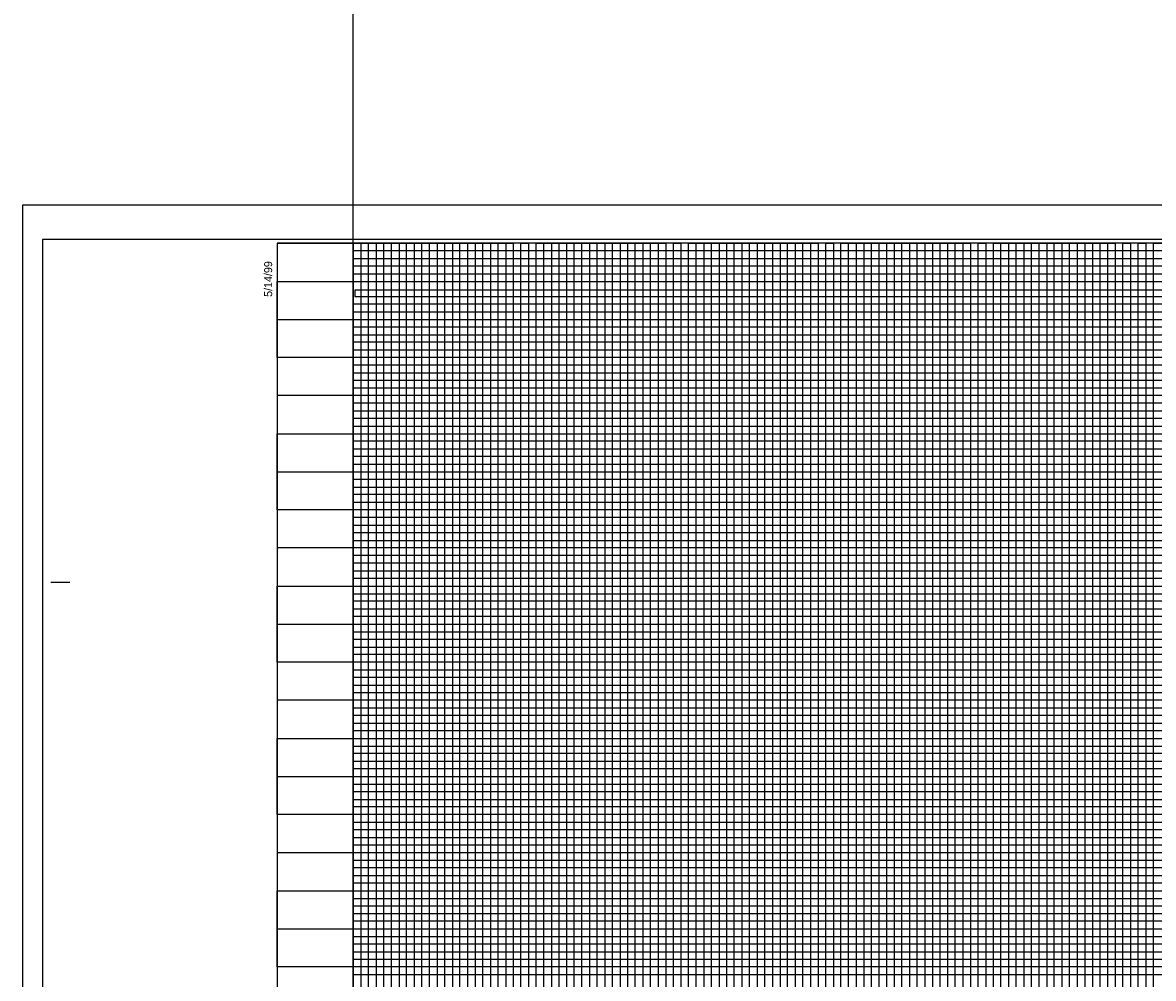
# Model space of a CAD drawing. Extents: x 2345490 to 2436403, y 465165 to 573888.
# Drawn here: x 2381550 to 2382292, y 532954 to 533581 of the extents above; entities that cross this region are included whole.
import ezdxf

# ---------------------------------------------------------------- set-up
doc = ezdxf.new("R2010")
doc.units = 0
for name, color, linetype in [('Old_Level_18', 7, 'Continuous'), ('Old_Level_41', 7, 'Continuous'), ('Old_Level_42', 7, 'Continuous'), ('Old_Level_43', 7, 'Continuous'), ('Old_Level_50', 7, 'Continuous'), ('Old_Level_51', 7, 'Continuous'), ('Old_Level_63', 7, 'Continuous')]:
    doc.layers.add(name, color=color, linetype=linetype)

msp = doc.modelspace()

# ---------------------------------------------------------------- linework, layer by layer
at = {"layer": 'Old_Level_18'}
msp.add_lwpolyline([(2383216.79875, 533436.04975), (2381716.79875, 533436.04975), (2381716.79875, 532386.04975), (2383216.79875, 532386.04975)], close=True, dxfattribs=at)
at = {"layer": 'Old_Level_41'}
msp.add_line((2381568.29875, 533213.54975), (2381580.79875, 533213.54975), dxfattribs=at)
for points in [[(2381716.79875, 533436.04975), (2381766.79875, 533436.04975), (2381766.79875, 532411.04975), (2381816.79875, 532411.04975), (2381816.79875, 533436.04975), (2381866.79875, 533436.04975), (2381866.79875, 532411.04975), (2381916.79875, 532411.04975), (2381916.79875, 533436.04975), (2381966.79875, 533436.04975), (2381966.79875, 532411.04975), (2382016.79875, 532411.04975), (2382016.79875, 533436.04975), (2382066.79875, 533436.04975), (2382066.79875, 532411.04975), (2382116.79875, 532411.04975), (2382116.79875, 533436.04975), (2382166.79875, 533436.04975), (2382166.79875, 532411.04975), (2382216.79875, 532411.04975), (2382216.79875, 533436.04975), (2382266.79875, 533436.04975), (2382266.79875, 532411.04975), (2382316.79875, 532411.04975)], [(2381791.79875, 532411.04975), (2381791.79875, 533436.04975), (2381841.79875, 533436.04975), (2381841.79875, 532411.04975), (2381891.79875, 532411.04975), (2381891.79875, 533436.04975), (2381941.79875, 533436.04975), (2381941.79875, 532411.04975), (2381991.79875, 532411.04975), (2381991.79875, 533436.04975), (2382041.79875, 533436.04975), (2382041.79875, 532411.04975), (2382091.79875, 532411.04975), (2382091.79875, 533436.04975), (2382141.79875, 533436.04975), (2382141.79875, 532411.04975), (2382191.79875, 532411.04975), (2382191.79875, 533436.04975), (2382241.79875, 533436.04975), (2382241.79875, 532411.04975), (2382291.79875, 532411.04975), (2382291.79875, 533436.04975), (2382341.79875, 533436.04975)], [(2381716.79875, 533386.04975), (2383016.74875, 533386.04975)], [(2383016.74875, 533336.04975), (2381716.79875, 533336.04975), (2381716.79875, 533285.99975), (2383216.79875, 533285.99975)], [(2383216.79875, 533261.04975), (2381716.79875, 533261.04975), (2381716.79875, 533311.04975), (2383016.74875, 533311.04975)], [(2383216.79875, 533236.04975), (2381716.79875, 533236.04975), (2381716.79875, 533186.04975), (2383216.79875, 533186.04975)], [(2383216.79875, 533161.04975), (2381716.79875, 533161.04975), (2381716.79875, 533211.04975), (2383216.79875, 533211.04975)], [(2383216.79875, 533136.04975), (2381716.79875, 533136.04975), (2381716.79875, 533086.04975), (2383216.79875, 533086.04975)], [(2383216.79875, 533036.04975), (2381716.79875, 533036.04975), (2381716.79875, 532986.04975), (2383216.79875, 532986.04975)]]:
    msp.add_lwpolyline(points, dxfattribs=at)
at = {"layer": 'Old_Level_42'}
for points in [[(2383016.74875, 533361.04975), (2381716.89875, 533361.04975), (2381716.89875, 533410.99975), (2383016.74875, 533410.99975)], [(2383216.79875, 533061.04975), (2381716.79875, 533061.04975), (2381716.79875, 533111.04975), (2383216.79875, 533111.04975)], [(2383216.79875, 532961.04975), (2381716.79875, 532961.04975), (2381716.79875, 533011.04975), (2383216.79875, 533011.04975)]]:
    msp.add_lwpolyline(points, dxfattribs=at)
at = {"layer": 'Old_Level_43'}
for p, q in [((2383166.79875, 533256.04975), (2381766.79875, 533256.04975)), ((2381766.79875, 533256.04975), (2381766.79875, 533251.04975)), ((2381766.79875, 533251.04975), (2383166.79875, 533251.04975)), ((2383166.79875, 533231.04975), (2381766.79875, 533231.04975))]:
    msp.add_line(p, q, dxfattribs=at)
for points in [[(2381771.79875, 533436.04975), (2381776.79875, 533436.04975), (2381781.79875, 533436.04975), (2381786.79875, 533436.04975), (2381796.79875, 533436.04975), (2381763.74875, 533436.04975), (2381768.74875, 533436.04975), (2381726.79875, 533436.04975), (2381731.79875, 533436.04975), (2381736.79875, 533436.04975), (2381746.79875, 533436.04975), (2381751.79875, 533436.04975), (2381756.79875, 533436.04975), (2381761.79875, 533436.04975), (2381771.79875, 533436.04975), (2381771.79875, 532411.04975)], [(2381776.79875, 532411.04975), (2381776.79875, 533436.04975), (2381781.79875, 533436.04975), (2381781.79875, 532411.04975)], [(2381786.79875, 532411.04975), (2381786.79875, 533436.04975), (2381796.79875, 533436.04975), (2381796.79875, 532411.04975)], [(2381801.79875, 532411.04975), (2381801.79875, 533436.04975), (2381806.79875, 533436.04975), (2381806.79875, 532411.04975)], [(2381811.79875, 532411.04975), (2381811.79875, 533436.04975), (2381821.79875, 533436.04975), (2381821.79875, 532411.04975)], [(2381826.79875, 532411.04975), (2381826.79875, 533436.04975), (2381831.79875, 533436.04975), (2381831.79875, 532411.04975)], [(2381836.79875, 532411.04975), (2381836.79875, 533436.04975), (2381846.79875, 533436.04975), (2381846.79875, 532411.04975)], [(2381851.79875, 532411.04975), (2381851.79875, 533436.04975), (2381856.79875, 533436.04975), (2381856.79875, 532411.04975)], [(2381861.79875, 532411.04975), (2381861.79875, 533436.04975), (2381871.79875, 533436.04975), (2381871.79875, 532411.04975)], [(2381876.79875, 532411.04975), (2381876.79875, 533436.04975), (2381881.79875, 533436.04975), (2381881.79875, 532411.04975)], [(2381886.79875, 532411.04975), (2381886.79875, 533436.04975), (2381896.79875, 533436.04975), (2381896.79875, 532411.04975)], [(2381901.79875, 532411.04975), (2381901.79875, 533436.04975), (2381906.79875, 533436.04975), (2381906.79875, 532411.04975)], [(2381911.79875, 532411.04975), (2381911.79875, 533436.04975), (2381921.79875, 533436.04975), (2381921.79875, 532411.04975)], [(2381926.79875, 532411.04975), (2381926.79875, 533436.04975), (2381931.79875, 533436.04975), (2381931.79875, 532411.04975)], [(2381936.79875, 532411.04975), (2381936.79875, 533436.04975), (2381946.79875, 533436.04975), (2381946.79875, 532411.04975)], [(2381951.79875, 532411.04975), (2381951.79875, 533436.04975), (2381956.79875, 533436.04975), (2381956.79875, 532411.04975)], [(2381961.79875, 532411.04975), (2381961.79875, 533436.04975), (2381971.79875, 533436.04975), (2381971.79875, 532411.04975)], [(2381976.79875, 532411.04975), (2381976.79875, 533436.04975), (2381976.79875, 533436.04975), (2381981.79875, 533436.04975), (2381981.79875, 532411.04975)], [(2381986.79875, 532411.04975), (2381986.79875, 533436.04975), (2381996.79875, 533436.04975), (2381996.79875, 532411.04975)], [(2382001.79875, 532411.04975), (2382001.79875, 533436.04975), (2382006.79875, 533436.04975), (2382006.79875, 532411.04975)], [(2382011.79875, 532411.04975), (2382011.79875, 533436.04975), (2382021.79875, 533436.04975), (2382021.79875, 532411.04975)], [(2382026.79875, 532411.04975), (2382026.79875, 533436.04975), (2382031.79875, 533436.04975), (2382031.79875, 532411.04975)], [(2382036.79875, 532411.04975), (2382036.79875, 533436.04975), (2382046.79875, 533436.04975), (2382046.79875, 532411.04975)], [(2382051.79875, 532411.04975), (2382051.79875, 533436.04975), (2382056.79875, 533436.04975), (2382056.79875, 532411.04975)], [(2382061.79875, 532411.04975), (2382061.79875, 533436.04975), (2382071.79875, 533436.04975), (2382071.79875, 532411.04975)], [(2382076.79875, 532411.04975), (2382076.79875, 533436.04975), (2382081.79875, 533436.04975), (2382081.79875, 532411.04975)], [(2382086.79875, 532411.04975), (2382086.79875, 533436.04975), (2382096.79875, 533436.04975), (2382096.79875, 532411.04975)], [(2382101.79875, 533436.04975), (2382101.79875, 532411.04975), (2382106.79875, 532411.04975), (2382106.79875, 533436.04975)], [(2382101.79875, 533435.44975), (2382101.79875, 532411.04975), (2382106.79875, 532411.04975), (2382106.79875, 533435.44975)], [(2382111.79875, 532411.04975), (2382111.79875, 533436.04975), (2382121.79875, 533436.04975), (2382121.79875, 532411.04975)], [(2382126.79875, 532411.04975), (2382126.79875, 533436.04975), (2382131.79875, 533436.04975), (2382131.79875, 532411.04975)], [(2382136.79875, 532411.04975), (2382136.79875, 533436.04975), (2382146.79875, 533436.04975), (2382146.79875, 532411.04975)], [(2382151.79875, 532411.04975), (2382151.79875, 533436.04975), (2382156.79875, 533436.04975), (2382156.79875, 532411.04975)], [(2382161.79875, 532411.04975), (2382161.79875, 533436.04975), (2382171.79875, 533436.04975), (2382171.79875, 532411.04975)], [(2382176.79875, 532411.04975), (2382176.79875, 533436.04975), (2382181.79875, 533436.04975), (2382181.79875, 532411.04975)], [(2382186.79875, 532411.04975), (2382186.79875, 533436.04975), (2382196.79875, 533436.04975), (2382196.79875, 532411.04975)], [(2382201.79875, 532411.04975), (2382201.79875, 533436.04975), (2382206.79875, 533436.04975), (2382206.79875, 532411.04975)], [(2382211.79875, 532411.04975), (2382211.79875, 533436.04975), (2382221.79875, 533436.04975), (2382221.79875, 532411.04975)], [(2382226.79875, 532411.04975), (2382226.79875, 533436.04975), (2382231.79875, 533436.04975), (2382231.79875, 532411.04975)], [(2382236.79875, 532411.04975), (2382236.79875, 533436.04975), (2382246.79875, 533436.04975), (2382246.79875, 532411.04975)], [(2382251.79875, 533436.04975), (2382251.79875, 532411.04975), (2382256.79875, 532411.04975), (2382256.79875, 533436.04975), (2382261.79875, 533436.04975), (2382261.79875, 532411.04975), (2382271.79875, 532411.04975), (2382271.79875, 533436.04975), (2382276.79875, 533436.04975), (2382276.79875, 532411.04975), (2382281.79875, 532411.04975), (2382281.79875, 533436.04975), (2382286.79875, 533436.04975), (2382286.79875, 532411.04975)], [(2383016.74875, 533431.04975), (2381766.79875, 533431.04975), (2381766.79875, 533426.04975), (2383016.74875, 533426.04975)], [(2383016.74875, 533421.04975), (2381766.79875, 533421.04975), (2381766.79875, 533416.04975), (2383016.74875, 533416.04975)], [(2383016.74875, 533405.29975), (2381767.79875, 533405.29975), (2381767.79875, 533401.04975), (2383016.74875, 533401.04975)], [(2383016.74875, 533396.04975), (2381766.79875, 533396.04975), (2381766.79875, 533391.04975), (2383016.74875, 533391.04975)], [(2383016.74875, 533381.04975), (2381766.79875, 533381.04975), (2381766.79875, 533376.04975), (2383016.74875, 533376.04975)], [(2383016.74875, 533371.04975), (2381766.79875, 533371.04975), (2381766.79875, 533366.04975), (2383016.74875, 533366.04975)], [(2383016.74875, 533356.04975), (2381766.79875, 533356.04975), (2381766.79875, 533351.04975), (2383016.74875, 533351.04975)], [(2383016.74875, 533346.04975), (2381766.79875, 533346.04975), (2381766.79875, 533341.04975), (2383016.74875, 533341.04975)], [(2383016.74875, 533331.04975), (2381766.79875, 533331.04975), (2381766.79875, 533326.04975), (2383016.74875, 533326.04975)], [(2383016.74875, 533321.04975), (2381766.79875, 533321.04975), (2381766.79875, 533316.04975), (2383016.74875, 533316.04975)], [(2383016.74875, 533306.04975), (2381766.79875, 533306.04975), (2381766.79875, 533301.04975), (2383016.74875, 533301.04975)], [(2383166.79875, 533296.04975), (2381766.79875, 533296.04975), (2381766.79875, 533296.04975), (2381766.79875, 533276.04975), (2383166.79875, 533276.04975)], [(2381766.79875, 533291.04975), (2383166.79875, 533291.04975)], [(2383166.79875, 533281.04975), (2381766.79875, 533281.04975)], [(2383166.79875, 533271.04975), (2381766.79875, 533271.04975), (2381766.79875, 533266.04975), (2383166.79875, 533266.04975)], [(2383166.79875, 533246.04975), (2381766.79875, 533246.04975), (2381766.79875, 533241.04975), (2383166.79875, 533241.04975)], [(2383166.79875, 533226.04975), (2381766.79875, 533226.04975), (2381766.79875, 533221.04975), (2383166.79875, 533221.04975)], [(2383166.79875, 533216.04975), (2381766.79875, 533216.04975)], [(2381766.79875, 533206.04975), (2383166.79875, 533206.04975)], [(2383166.79875, 533201.04975), (2381766.79875, 533201.04975), (2381766.79875, 533196.04975), (2383166.79875, 533196.04975)], [(2383166.79875, 533191.04975), (2381766.79875, 533191.04975), (2381766.79875, 533181.04975), (2383166.79875, 533181.04975)], [(2383166.79875, 533176.04975), (2381766.79875, 533176.04975), (2381766.79875, 533171.04975), (2383166.79875, 533171.04975)], [(2383166.79875, 533166.04975), (2381766.79875, 533166.04975), (2381766.79875, 533156.04975), (2383166.79875, 533156.04975)], [(2383166.79875, 533151.04975), (2381766.79875, 533151.04975), (2381766.79875, 533146.04975), (2383166.79875, 533146.04975)], [(2383166.79875, 533141.04975), (2381766.79875, 533141.04975), (2381766.79875, 533131.04975), (2383166.79875, 533131.04975)], [(2383166.79875, 533126.04975), (2381766.79875, 533126.04975), (2381766.79875, 533121.04975), (2383166.79875, 533121.04975)], [(2383166.79875, 533116.04975), (2381766.79875, 533116.04975), (2381766.79875, 533106.04975), (2383166.79875, 533106.04975)], [(2383166.79875, 533101.04975), (2381766.79875, 533101.04975), (2381766.79875, 533096.04975), (2383166.79875, 533096.04975)], [(2383166.79875, 533091.04975), (2381766.79875, 533091.04975), (2381766.79875, 533081.04975), (2383166.79875, 533081.04975)], [(2383166.79875, 533076.04975), (2381766.79875, 533076.04975), (2381766.79875, 533071.04975), (2383166.79875, 533071.04975)], [(2383166.79875, 533066.04975), (2381766.79875, 533066.04975), (2381766.79875, 533056.04975), (2383166.79875, 533056.04975)], [(2383166.79875, 533051.04975), (2381766.79875, 533051.04975), (2381766.79875, 533046.04975), (2383166.79875, 533046.04975)], [(2383166.79875, 533041.04975), (2381766.79875, 533041.04975), (2381766.79875, 533031.04975), (2383166.79875, 533031.04975)], [(2383166.79875, 533026.04975), (2381766.79875, 533026.04975), (2381766.79875, 533021.04975), (2383166.79875, 533021.04975)], [(2383166.79875, 533016.04975), (2381766.79875, 533016.04975), (2381766.79875, 533006.04975), (2383166.79875, 533006.04975)], [(2383166.79875, 533001.04975), (2381766.79875, 533001.04975), (2381766.79875, 532996.04975), (2383166.79875, 532996.04975)], [(2383166.79875, 532991.04975), (2381766.79875, 532991.04975), (2381766.79875, 532981.04975), (2383166.79875, 532981.04975)], [(2383166.79875, 532976.04975), (2381766.79875, 532976.04975), (2381766.79875, 532971.04975), (2383166.79875, 532971.04975)], [(2383166.79875, 532966.04975), (2381766.79875, 532966.04975), (2381766.79875, 532956.04975), (2383166.79875, 532956.04975)]]:
    msp.add_lwpolyline(points, dxfattribs=at)
at = {"layer": 'Old_Level_50'}
msp.add_lwpolyline([(2383229.29875, 533438.59975), (2381562.79875, 533438.59975), (2381562.79875, 532383.49975), (2383229.29875, 532383.49975)], close=True, dxfattribs=at)
at = {"layer": 'Old_Level_51'}
msp.add_lwpolyline([(2383233.79875, 533461.04975), (2381549.79875, 533461.04975), (2381549.79875, 532361.04975), (2383233.79875, 532361.04975)], close=True, dxfattribs=at)
at = {"layer": 'Old_Level_63'}
msp.add_line((2381766.79875, 532411.04975), (2381766.79875, 534911.04975), dxfattribs=at)

# ---------------------------------------------------------------- texts
at = {"layer": 'Old_Level_41'}
msp.add_text('5/14/99', height=5.25, rotation=90, dxfattribs=at).set_placement((2381713.54875, 533400.84975))

doc.saveas('drawing.dxf')
